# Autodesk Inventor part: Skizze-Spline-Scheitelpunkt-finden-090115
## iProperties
Category: Zeichnung
Manager: Dr.-Ing. Roland Schröder
Company: Das Entwicklungsbuero
Created: 2009-01
Part Number: Skizze-Spline-Scheitelpunkt-finden-090115
Document SubType Name: Modeling
Designer: Roland
Density: 1 g/cm^3
Author: Roland
